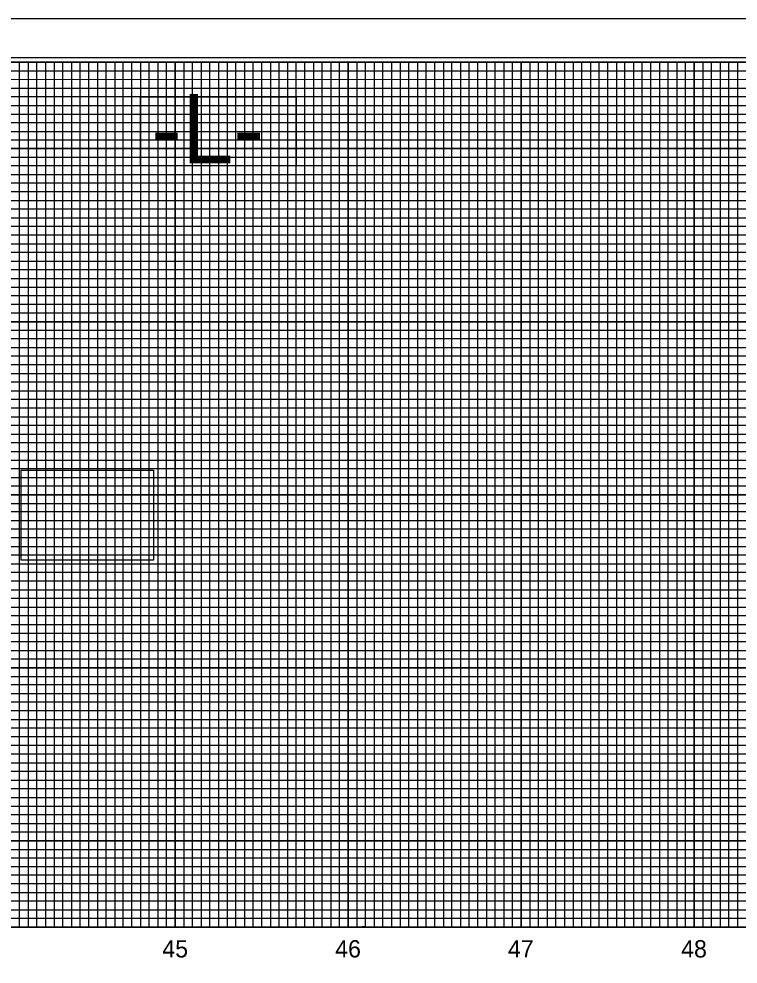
# Model space of a CAD drawing. Extents: x 1779926 to 1781610, y 620464 to 621564.
# Drawn here: x 1780753 to 1781168, y 621018 to 621564 of the extents above; entities that cross this region are included whole.
import ezdxf

# ---------------------------------------------------------------- set-up
doc = ezdxf.new("R2010")
doc.units = 0
for name, color, linetype in [('Exist Vertical Profile Horizontal Axis Label Major', 7, 'Continuous'), ('Exist Vertical Profile Vertical Axis Label', 7, 'Continuous'), ('Prop Grid Mask', 7, 'Continuous'), ('Scratch_Level_0', 7, 'Continuous'), ('Sheet Cutting Line CELL', 7, 'Continuous'), ('Sheet DOT Grid CELL', 7, 'Continuous'), ('Sheet Layout Profile Border Port 1', 7, 'Continuous'), ('Sheet Plot Border Inside CELL', 7, 'Continuous'), ('Sheet Plot Border Outside CELL', 7, 'Continuous'), ('Sheet Profile CELL', 7, 'Continuous'), ('Sheet Profile Grid Major CELL', 7, 'Continuous'), ('Sheet Profile Grid Middle CELL', 7, 'Continuous'), ('Sheet Profile Grid Minor CELL', 7, 'Continuous')]:
    doc.layers.add(name, color=color, linetype=linetype)

msp = doc.modelspace()

# ---------------------------------------------------------------- linework, layer by layer
at = {"layer": 'Prop Grid Mask'}
for points in [[(1780822.96, 621519.19), (1780912.96, 621519.19), (1780912.96, 621479.19), (1780822.96, 621479.19)], [(1780753.95, 621303.41), (1780830.41, 621303.41), (1780830.41, 621251.39), (1780753.95, 621251.39)]]:
    msp.add_lwpolyline(points, close=True, dxfattribs=at)
at = {"layer": 'Scratch_Level_0'}
msp.add_lwpolyline([(1780142.96, 621039.19), (1780142.96, 621539.19), (1781392.96, 621539.19), (1781392.96, 621314.19), (1781542.96, 621314.19), (1781542.96, 621039.19)], close=True, dxfattribs=at)
at = {"layer": 'Sheet Cutting Line CELL'}
msp.add_line((1781609.96, 621564.19), (1779925.96, 621564.19), dxfattribs=at)
at = {"layer": 'Sheet DOT Grid CELL'}
for p, q in [((1780792.96, 621039.19), (1780792.96, 621539.19)), ((1780842.96, 621039.19), (1780842.96, 621539.19)), ((1780892.96, 621039.19), (1780892.96, 621539.19)), ((1780942.96, 621039.19), (1780942.96, 621539.19)), ((1780992.96, 621039.19), (1780992.96, 621539.19)), ((1781042.96, 621039.19), (1781042.96, 621539.19)), ((1781092.96, 621039.19), (1781092.96, 621539.19)), ((1781142.96, 621039.19), (1781142.96, 621539.19)), ((1781392.91, 621489.19), (1780092.96, 621489.19)), ((1781392.91, 621439.19), (1780092.96, 621439.19)), ((1781392.96, 621389.19), (1780092.96, 621389.19)), ((1781392.91, 621339.19), (1780092.96, 621339.19)), ((1781592.96, 621289.19), (1780092.96, 621289.19)), ((1781592.96, 621239.19), (1780092.96, 621239.19)), ((1781592.96, 621189.19), (1780092.96, 621189.19)), ((1781592.96, 621139.19), (1780092.96, 621139.19)), ((1781592.96, 621089.19), (1780092.96, 621089.19))]:
    msp.add_line(p, q, dxfattribs=at)
at = {"layer": 'Sheet Layout Profile Border Port 1'}
msp.add_lwpolyline([(1780142.96, 621378.14), (1780142.96, 621039.19), (1781542.96, 621039.19), (1781542.96, 621314.19)], dxfattribs=at)
at = {"layer": 'Sheet Plot Border Inside CELL'}
msp.add_lwpolyline([(1779938.96, 620486.64), (1781605.46, 620486.64), (1781605.46, 621541.74), (1779938.96, 621541.74)], close=True, dxfattribs=at)
at = {"layer": 'Sheet Plot Border Outside CELL'}
msp.add_lwpolyline([(1779925.96, 620464.19), (1781609.96, 620464.19), (1781609.96, 621564.19), (1779925.96, 621564.19)], close=True, dxfattribs=at)
at = {"layer": 'Sheet Profile CELL'}
msp.add_line((1780092.96, 621039.19), (1781592.96, 621039.19), dxfattribs=at)
msp.add_lwpolyline([(1781592.96, 621539.19), (1780092.96, 621539.19), (1780092.96, 620489.19), (1781592.96, 620489.19)], close=True, dxfattribs=at)
at = {"layer": 'Sheet Profile Grid Major CELL'}
for points in [[(1780742.96, 621039.19), (1780792.96, 621039.19), (1780792.96, 621539.19), (1780842.96, 621539.19), (1780842.96, 621039.19), (1780892.96, 621039.19), (1780892.96, 621539.19), (1780942.96, 621539.19), (1780942.96, 621039.19), (1780992.96, 621039.19), (1780992.96, 621539.19), (1781042.96, 621539.19), (1781042.96, 621039.19), (1781092.96, 621039.19), (1781092.96, 621539.19), (1781142.96, 621539.19), (1781142.96, 621039.19), (1781192.96, 621039.19)], [(1780092.96, 621489.19), (1781392.96, 621489.19)], [(1781392.96, 621439.19), (1780092.96, 621439.19), (1780092.96, 621389.19), (1781392.96, 621389.19)], [(1781392.91, 621339.19), (1780092.96, 621339.19), (1780092.96, 621289.19), (1781592.96, 621289.19)], [(1781592.96, 621239.19), (1780092.96, 621239.19), (1780092.96, 621189.19), (1781592.96, 621189.19)], [(1781592.96, 621139.19), (1780092.96, 621139.19), (1780092.96, 621139.19), (1780092.96, 621089.19), (1781592.96, 621089.19)]]:
    msp.add_lwpolyline(points, dxfattribs=at)
at = {"layer": 'Sheet Profile Grid Middle CELL'}
msp.add_line((1780092.96, 621514.19), (1781392.91, 621514.19), dxfattribs=at)
for points in [[(1780717.96, 621539.19), (1780767.96, 621539.19), (1780767.96, 621039.19), (1780817.96, 621039.19), (1780817.96, 621539.19), (1780867.96, 621539.19), (1780867.96, 621039.19), (1780917.96, 621039.19), (1780917.96, 621539.19), (1780967.96, 621539.19), (1780967.96, 621039.19), (1781017.96, 621039.19), (1781017.96, 621539.19), (1781067.96, 621539.19), (1781067.96, 621039.19), (1781117.96, 621039.19), (1781117.96, 621539.19), (1781167.96, 621539.19), (1781167.96, 621039.19), (1781217.96, 621039.19)], [(1781392.96, 621464.19), (1780092.96, 621464.19), (1780092.96, 621414.19), (1781392.96, 621414.19)], [(1781392.91, 621364.19), (1780092.96, 621364.19), (1780092.96, 621314.19), (1781417.96, 621314.19)], [(1781592.96, 621264.19), (1780092.96, 621264.19), (1780092.96, 621214.19), (1781592.96, 621214.19)], [(1781592.96, 621164.19), (1780092.96, 621164.19), (1780092.96, 621114.19), (1781592.96, 621114.19)], [(1781592.96, 621064.19), (1780092.96, 621064.19)]]:
    msp.add_lwpolyline(points, dxfattribs=at)
at = {"layer": 'Sheet Profile Grid Minor CELL'}
for p, q in [((1780142.96, 621534.19), (1781392.96, 621534.19)), ((1781392.96, 621529.19), (1780142.96, 621528.84)), ((1780142.96, 621524.19), (1781392.96, 621524.19)), ((1781392.91, 621404.19), (1780142.96, 621404.19)), ((1781392.96, 621399.19), (1780142.96, 621399.19)), ((1781392.96, 621394.19), (1780142.96, 621394.19)), ((1780142.96, 621384.19), (1781392.96, 621384.19)), ((1781392.96, 621379.19), (1780142.96, 621379.19)), ((1780142.96, 621374.19), (1781392.96, 621374.19)), ((1781392.96, 621354.19), (1780142.96, 621354.19)), ((1780142.96, 621349.19), (1781392.96, 621349.19)), ((1781392.91, 621329.19), (1780142.96, 621329.19)), ((1780142.96, 621324.19), (1781392.91, 621324.19)), ((1781542.96, 621304.19), (1780142.96, 621304.19)), ((1780142.96, 621299.19), (1781542.96, 621299.19)), ((1781542.96, 621294.19), (1780142.96, 621294.19)), ((1780142.96, 621284.19), (1781542.96, 621284.19)), ((1781542.96, 621279.19), (1780142.96, 621279.19)), ((1780142.96, 621274.19), (1781542.96, 621274.19)), ((1781542.96, 621269.19), (1780142.96, 621269.19)), ((1780142.96, 621259.19), (1781542.96, 621259.19)), ((1781542.96, 621254.19), (1780142.96, 621254.19)), ((1780142.96, 621249.19), (1781542.96, 621249.19)), ((1781542.96, 621244.19), (1780142.96, 621244.19)), ((1780142.96, 621234.19), (1781542.96, 621234.19)), ((1781542.96, 621229.19), (1780142.96, 621229.19)), ((1780142.96, 621224.19), (1781542.96, 621224.19)), ((1781542.96, 621219.19), (1780142.96, 621219.19)), ((1780142.96, 621209.19), (1781542.96, 621209.19)), ((1781542.96, 621204.19), (1780142.96, 621204.19)), ((1780142.96, 621199.19), (1781542.96, 621199.19)), ((1781542.96, 621194.19), (1780142.96, 621194.19)), ((1780142.96, 621184.19), (1781542.96, 621184.19)), ((1781542.96, 621179.19), (1780142.96, 621179.19)), ((1780142.96, 621174.19), (1781542.96, 621174.19)), ((1781542.96, 621169.19), (1780142.96, 621169.19)), ((1780142.96, 621159.19), (1781542.96, 621159.19)), ((1781542.96, 621154.19), (1780142.96, 621154.19)), ((1781542.96, 621149.19), (1780142.96, 621149.19)), ((1781542.96, 621144.19), (1780142.96, 621144.19)), ((1780142.96, 621134.19), (1781542.96, 621134.19)), ((1781542.96, 621129.19), (1780142.96, 621129.19)), ((1780142.96, 621124.19), (1781542.96, 621124.19)), ((1781542.96, 621119.19), (1780142.96, 621119.19)), ((1780142.96, 621109.19), (1781542.96, 621109.19)), ((1781542.96, 621104.19), (1780142.96, 621104.19)), ((1780142.96, 621099.19), (1781542.96, 621099.19)), ((1781542.96, 621094.19), (1780142.96, 621094.19)), ((1780142.96, 621084.19), (1781542.96, 621084.19)), ((1781542.96, 621079.19), (1780142.96, 621079.19)), ((1780142.96, 621074.19), (1781542.96, 621074.19)), ((1781542.96, 621069.19), (1780142.96, 621069.19)), ((1780142.96, 621059.19), (1781542.96, 621059.19)), ((1781542.96, 621054.19), (1780142.96, 621054.19)), ((1780142.96, 621049.19), (1781542.96, 621049.19))]:
    msp.add_line(p, q, dxfattribs=at)
for points in [[(1780747.96, 621039.19), (1780752.96, 621039.19), (1780752.96, 621539.19), (1780757.96, 621539.19), (1780757.96, 621039.19), (1780762.96, 621039.19), (1780762.96, 621539.19), (1780772.96, 621539.19), (1780772.96, 621039.19), (1780777.96, 621039.19), (1780777.96, 621539.19), (1780782.96, 621539.19), (1780782.96, 621039.19), (1780787.96, 621039.19), (1780787.96, 621539.19), (1780797.96, 621539.19), (1780797.96, 621039.19), (1780797.96, 621039.19), (1780802.96, 621039.19), (1780802.96, 621539.19), (1780807.96, 621539.19), (1780807.96, 621039.19), (1780812.96, 621039.19), (1780812.96, 621539.19), (1780822.96, 621539.19), (1780822.96, 621039.19), (1780827.96, 621039.19), (1780827.96, 621539.19), (1780832.96, 621539.19), (1780832.96, 621039.19), (1780837.96, 621039.19), (1780837.96, 621539.19), (1780847.96, 621539.19), (1780847.96, 621039.19), (1780852.96, 621039.19), (1780852.96, 621539.19), (1780857.96, 621539.19), (1780857.96, 621039.19), (1780862.96, 621039.19), (1780862.96, 621539.19), (1780872.96, 621539.19), (1780872.96, 621039.19), (1780877.96, 621039.19), (1780877.96, 621539.19), (1780882.96, 621539.19), (1780882.96, 621039.19), (1780887.96, 621039.19), (1780887.96, 621539.19), (1780897.96, 621539.19), (1780897.96, 621039.19), (1780902.96, 621039.19), (1780902.96, 621539.19), (1780907.96, 621539.19), (1780907.96, 621039.19), (1780912.96, 621039.19), (1780912.96, 621539.19), (1780922.96, 621539.19), (1780922.96, 621039.19), (1780927.96, 621039.19), (1780927.96, 621539.19), (1780932.96, 621539.19), (1780932.96, 621039.19), (1780937.96, 621039.19), (1780937.96, 621539.19), (1780947.96, 621539.19), (1780947.96, 621039.19), (1780952.66, 621039.74), (1780952.96, 621039.19), (1780952.96, 621539.19), (1780957.96, 621539.19), (1780957.96, 621039.19), (1780962.96, 621039.19), (1780962.96, 621539.19), (1780972.96, 621539.19), (1780972.96, 621039.19), (1780977.96, 621039.19)], [(1780977.96, 621039.19), (1780977.96, 621539.19), (1780982.96, 621539.19), (1780982.96, 621039.19), (1780987.96, 621039.19), (1780987.96, 621539.19), (1780997.96, 621539.19), (1780997.96, 621039.19), (1781002.96, 621039.19), (1781002.96, 621539.19), (1781007.96, 621539.19), (1781007.96, 621039.19), (1781012.96, 621039.19), (1781012.96, 621539.19), (1781022.96, 621539.19), (1781022.96, 621039.19), (1781027.96, 621039.19), (1781027.96, 621539.19), (1781032.96, 621539.19), (1781032.96, 621039.19), (1781037.96, 621039.19), (1781037.96, 621539.19), (1781047.96, 621539.19), (1781047.96, 621039.19), (1781052.96, 621039.19), (1781052.96, 621539.19), (1781057.96, 621539.19), (1781057.96, 621039.19), (1781062.96, 621039.19), (1781062.96, 621539.19), (1781072.96, 621539.19), (1781072.96, 621039.19), (1781077.96, 621039.19), (1781077.96, 621539.19), (1781082.96, 621539.19), (1781082.96, 621039.19), (1781087.96, 621039.19), (1781087.96, 621539.19), (1781097.96, 621539.19), (1781097.96, 621039.19), (1781102.96, 621039.19), (1781102.96, 621539.19), (1781107.96, 621539.19), (1781107.96, 621039.19), (1781112.96, 621039.19), (1781112.96, 621539.19), (1781122.96, 621539.19), (1781122.96, 621039.19), (1781127.96, 621039.19), (1781127.96, 621539.19), (1781132.96, 621539.19), (1781132.96, 621039.19), (1781137.96, 621039.19), (1781137.96, 621539.19), (1781147.96, 621539.19), (1781147.96, 621039.19), (1781152.96, 621039.19), (1781152.96, 621539.19), (1781157.96, 621539.19), (1781157.96, 621039.19), (1781162.96, 621039.19), (1781162.96, 621539.19), (1781172.96, 621539.19)], [(1781392.96, 621519.19), (1780142.96, 621519.19), (1780142.96, 621509.19), (1781392.96, 621509.19)], [(1781392.91, 621504.19), (1780142.96, 621504.19), (1780142.96, 621499.19), (1781392.96, 621499.19)], [(1781392.96, 621494.19), (1780142.96, 621494.19), (1780142.96, 621484.19), (1781392.96, 621484.19)], [(1781392.96, 621479.19), (1780142.96, 621479.19), (1780142.96, 621474.19), (1781392.96, 621474.19)], [(1781392.96, 621469.19), (1780142.96, 621469.19), (1780142.96, 621459.19), (1781392.96, 621459.19)], [(1781392.96, 621454.19), (1780142.96, 621454.19), (1780142.96, 621449.19), (1781392.96, 621449.19)], [(1781392.96, 621444.19), (1780142.96, 621444.19), (1780142.96, 621434.19), (1781392.96, 621434.19)], [(1781392.96, 621429.09), (1780143.06, 621429.09), (1780143.06, 621424.19), (1781392.96, 621424.19)], [(1781392.96, 621419.19), (1780142.96, 621419.19), (1780142.96, 621409.19), (1781392.96, 621409.19)], [(1781392.91, 621369.19), (1780142.96, 621369.19), (1780142.96, 621359.19), (1781392.91, 621359.19)], [(1781392.91, 621344.19), (1780142.96, 621344.19), (1780142.96, 621334.19), (1781392.91, 621334.19)], [(1781392.91, 621319.19), (1780142.96, 621319.19), (1780142.96, 621309.19), (1781542.96, 621309.19)], [(1781542.96, 621044.19), (1780142.96, 621044.19)]]:
    msp.add_lwpolyline(points, dxfattribs=at)

# ---------------------------------------------------------------- texts
at = {"layer": 'Exist Vertical Profile Horizontal Axis Label Major'}
for s, p in [('45', (1780835.5, 621021.69)), ('46', (1780935.44, 621021.69)), ('47', (1781035.3, 621021.69)), ('48', (1781135.43, 621021.69))]:
    msp.add_text(s, height=10, dxfattribs=at).set_placement(p)
at = {"layer": 'Exist Vertical Profile Vertical Axis Label'}
msp.add_text('-L-', height=40, dxfattribs=at).set_placement((1780829.02, 621480.78))

doc.saveas('drawing.dxf')
